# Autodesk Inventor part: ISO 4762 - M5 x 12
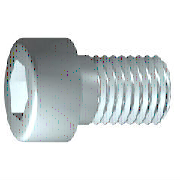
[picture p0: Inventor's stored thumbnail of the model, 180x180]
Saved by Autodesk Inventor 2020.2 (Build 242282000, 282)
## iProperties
Manager: www.cadconsulting.pl
Company: Fabian Stasiak CAD Consulting
Created: 2013-02
Part Number: ISO 4762 - M5 x 12
Material: Stal nierdzewna 440C
Description: Śruba z łbem o zmniejszonych z gniazdem sześciokątnym
Document SubType Name: Modeling
Standard: ISO 4762
Designer: F.Stasiak
Standard Revision: Fourth edition 2004-03-01
Standards Organization: ISO
Language: pl-PL
Size Designation: M5 x 12
Categories: <MemberInstance><Categories><Category DisplayName="Mocowania" InternalName="e4da775c-781d-43d5-af7c-5136215cf5a6" Mnemonic="FSTN"><Category DisplayName="Śruby"
Density: 7.75 g/cm^3
Appearance: Częściowo polerowana
Mass: 3.67607 g
Surface Area: 4.62573 cm^2
Volume: 0.474332 cm^3
IsCustomPart: 0
Author: F.Stasiak
Subject: Zbiór ćwiczeń. Autodesk Inventor 2020. Kurs podstawowy
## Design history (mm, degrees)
sketch "Szkic1"
  geometry: L1 (-1.167, 0)-(12, 0); L2 (12, 0)-(12, 2.5); L3 (12, 2.5)-(2, 2.5); L4 (2, 2.5)-(1.509, 2.5); L5 (1.509, 2.5)-(0, 2.5); L6 (0, 2.5)-(0, 4.25); L7 (0, 4.25)-(-5, 4.25); L8 (-5, 4.25)-(-5, 2.309); L9 (-5, 2.309)-(-2.5, 2.309); L10 (-2.5, 2.309)-(-1.167, 0); L11 (-8.4, 0)-(15.4, 0) reference; L12 (0, -0.85)-(0, 5.1) reference; L13 (2, 2.5)-(0, 2.5)
  constraints: 22 end point, 6 parallel, 2 collinear, 2 perpendicular, 1 horizontal, 1 point on line
  dimensions: "d1" = 10 distance from line of L3.end L2 (= GEL); "d2" = 0.49086 distance of L4.end L3.end (computed from GAL); "d3" = 5 distance between parallel lines of L8 L6 (= KOH); "d4" = 2.5 distance of L8.end L9.end (= INTI); "d5" = 60 deg angle of L10 L1; "d6" = 5 diameter of L3 L1 (= GD); "d7" = 5 diameter of L5 L1 (= BDM); "d8" = 4.6188 diameter of L9 L1 (= 1.1547 x SW); "d9" = 8.5 diameter of L7 L1 (= KOD); "d26" = 12 distance between parallel lines of L12 L2 (= NLG)
revolve "Bryła" sketch "Szkic1" stored, may be unused: angle "d10" = 90 deg
sketch "Szkic2"
  geometry: L1 (0, -5.95)-(0, 5.95) reference; L2 (-5.95, 0)-(5.95, 0) reference; L3 (2.309, 0)-(1.155, -2); L4 (1.155, -2)-(-1.155, -2); L5 (-1.155, -2)-(-2.309, 0); L6 (-2.309, 0)-(-1.155, 2); L7 (-1.155, 2)-(1.155, 2); L8 (1.155, 2)-(2.309, 0); 2 further points
  constraints: 12 end point, 1 coincident, 1 horizontal alignment, 1 point on line, 12 other
extrude "Szczelina" join sketch "Szkic2" stored distance "d11" = 10; taper "d12" = 0 deg
workplane "Work Plane1"
fillet "Fillet2" dims "d30" = 0.1 (= R)
body "Solid1"
fillet "Zaokrąglenie1" dims "d17" = 0.5 (= RR)
feature "Gwint" dims "d13" = 10 (= GEL), "d14" = 0
chamfer "Faza1" distance "d15" = 0.49076 (= -0.5 x SPD + 0.5 x GD); stored, may be unused: second distance "d16" = 0.49076 (= GUL), angle "d27" = 45 deg
other parameters: "GD" = 5 [user parameter; used in 2 equation terms], "NLG" = 12 [user parameter; used in 1 equation term], "GEL" = 10 [user parameter; used in 2 equation terms], "KOD" = 8.5 [user parameter; used in 1 equation term], "KOH" = 5 [user parameter; used in 1 equation term], "INTI" = 2.5 [user parameter; used in 1 equation term], "GAL" = 0.49076 (= 0.61345 x PTC) [user parameter; used in 1 equation term], "GUL" = 0.49076 (= 0.61345 x PTC) [user parameter; used in 1 equation term], "BDM" = 5 (= NND) [user parameter; used in 1 equation term], "SW" = 4 [user parameter; used in 2 equation terms], "RR" = 0.5 [user parameter; used in 1 equation term], "SPD" = 4.01848 (= NND - 1.2269 x PTC) [user parameter; used in 1 equation term], "d19" = 0, "d28" = 0, "d29" = 0, "R" = 0.1 [user parameter; used in 1 equation term], "TOA" = 30 deg [user parameter], "GD1" = 4.01848 (= THREADDIA - 1.2269 x PTC) [user parameter], "THREADDIA" = 5 [user parameter; used in 1 equation term], "FAWI" = 45 deg [user parameter], "TPU" = 12.5 (computed from PTC) [user parameter], "PTC" = 0.8 [user parameter; used in 5 equation terms], "NND" = 5 [user parameter; used in 2 equation terms], "E0" = 4.62 (= 1.155 x SW) [user parameter]
